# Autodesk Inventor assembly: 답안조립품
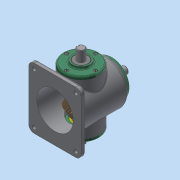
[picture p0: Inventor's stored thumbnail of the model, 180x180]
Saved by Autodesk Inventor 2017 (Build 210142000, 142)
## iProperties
Part Number: 답안조립품
Material: 일반
Document SubType Name: Assembly
Designer: MRC
Author: MRC
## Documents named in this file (16)
- C:\Users\MRC\Desktop\710116V1002\답안조립품.iam
- C:\Users\MRC\Desktop\710116V1002\본체.ipt
- C:\Users\MRC\Desktop\710116V1002\메인 베벨기어.ipt
- C:\Users\MRC\Desktop\710116V1002\메인 축.ipt
- 메인 축.ipt
- C:\Users\MRC\Desktop\710116V1002\베어링 6203.ipt
- C:\Users\MRC\Desktop\710116V1002\볼트 M4.ipt
- 볼트 M4.ipt
- C:\Users\MRC\Desktop\710116V1002\서브 베벨기어.ipt
- C:\Users\MRC\Desktop\710116V1002\서브 축.ipt
- 서브 축.ipt
- C:\Users\MRC\Desktop\710116V1002\오일 실.ipt
- 오일 실.ipt
- C:\Users\MRC\Desktop\710116V1002\커버.ipt
- C:\Users\MRC\Desktop\710116V1002\키 4x4.ipt
- C:\Users\MRC\Desktop\710116V1002\키 5x5.ipt
